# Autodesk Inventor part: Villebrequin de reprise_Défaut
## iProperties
Shininess: 64.0
Length Units: 11269
Angle Units: 11279
Time Units: 11290
Mass Units: 11283
Length Display Precision: 3
Angle Display Precision: 2
Compacted: True
Part Number: Villebrequin de reprise_Défaut
Document SubType Name: Modeling
Created: 2006-01
Material: Par défaut
Designer: riri
Density: 0.0
Volumn: 0.0
Area: 0.0
PropertySet Name: Model Information
Control State: 0
Master: False
Checked Out: False
Author: riri
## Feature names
1. Base1
